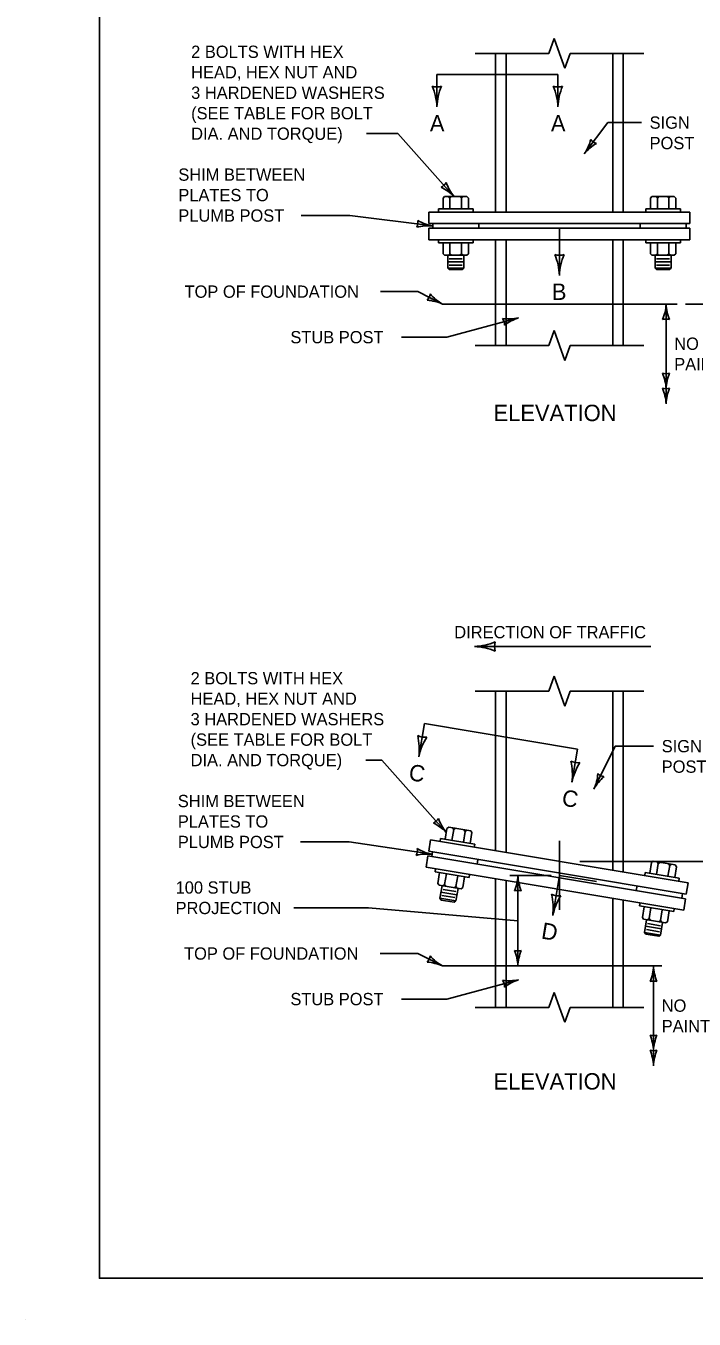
# Model space of a CAD drawing. Extents: x 49991.4 to 50021, y 49987.6 to 50011.4.
# Drawn here: x 49999.02 to 50002.29, y 49987.6 to 49993.92 of the extents above; entities that cross this region are included whole.
import ezdxf

# ---------------------------------------------------------------- set-up
doc = ezdxf.new("R2010")
doc.units = 0
for name, color, linetype in [('Level 1', 7, 'Continuous'), ('Level 2', 7, 'Continuous'), ('Level 3', 7, 'Continuous'), ('Level 5', 7, 'Continuous'), ('Level 6', 7, 'Continuous')]:
    doc.layers.add(name, color=color, linetype=linetype)

msp = doc.modelspace()

# ---------------------------------------------------------------- linework, layer by layer
at = {"layer": 'Level 1'}
for p, q in [((50001.3176, 49993.7824), (50001.3176, 49993.0073)), ((50001.3693, 49993.7824), (50001.3693, 49993.0073)), ((50001.8899, 49993.7824), (50001.8899, 49993.0073)), ((50001.9416, 49993.7824), (50001.9416, 49993.0073)), ((50001.069, 49993.0832), (50001.0615, 49993.0757)), ((50001.0615, 49993.0223), (50001.0615, 49993.0757)), ((50001.069, 49993.0832), (50001.1777, 49993.0832)), ((50001.0877, 49993.0832), (50001.0952, 49993.0757)), ((50001.1028, 49993.0832), (50001.0952, 49993.0757)), ((50001.0952, 49993.0223), (50001.0952, 49993.0757)), ((50001.144, 49993.0832), (50001.1515, 49993.0757)), ((50001.159, 49993.0832), (50001.1515, 49993.0757)), ((50001.1515, 49993.0223), (50001.1515, 49993.0757)), ((50001.1777, 49993.0832), (50001.1852, 49993.0757)), ((50001.1852, 49993.0757), (50001.1852, 49993.0223)), ((50002.0815, 49993.0832), (50002.074, 49993.0757)), ((50002.074, 49993.0757), (50002.074, 49993.0223)), ((50002.1902, 49993.0832), (50002.0815, 49993.0832)), ((50002.1002, 49993.0832), (50002.1077, 49993.0757)), ((50002.1152, 49993.0832), (50002.1077, 49993.0757)), ((50002.1077, 49993.0223), (50002.1077, 49993.0757)), ((50002.1564, 49993.0832), (50002.164, 49993.0757)), ((50002.1715, 49993.0832), (50002.164, 49993.0757)), ((50002.164, 49993.0223), (50002.164, 49993.0757)), ((50002.1902, 49993.0832), (50002.1977, 49993.0757)), ((50002.1977, 49993.0223), (50002.1977, 49993.0757)), ((50000.9922, 49993.0073), (50002.267, 49993.0073)), ((50000.9922, 49993.0073), (50000.9922, 49992.9512)), ((50001.039, 49993.0223), (50001.2077, 49993.0223)), ((50001.039, 49993.0223), (50001.039, 49993.0073)), ((50001.2077, 49993.0223), (50001.2077, 49993.0073)), ((50002.2202, 49993.0223), (50002.0515, 49993.0223)), ((50002.0515, 49993.0223), (50002.0515, 49993.0073)), ((50002.2202, 49993.0223), (50002.2202, 49993.0073)), ((50002.267, 49993.0073), (50002.267, 49992.9512)), ((50000.9922, 49992.9512), (50002.267, 49992.9512)), ((50000.9922, 49992.928), (50002.267, 49992.928)), ((50000.9922, 49992.928), (50000.9922, 49992.8717)), ((50001.0109, 49992.928), (50001.0109, 49992.9512)), ((50001.2359, 49992.928), (50001.2359, 49992.9512)), ((50002.0233, 49992.928), (50002.0233, 49992.9512)), ((50002.2483, 49992.928), (50002.2483, 49992.9512)), ((50002.267, 49992.928), (50002.267, 49992.8717)), ((50002.267, 49992.8717), (50000.9922, 49992.8717)), ((50001.039, 49992.8568), (50001.039, 49992.8717)), ((50001.039, 49992.8568), (50001.2077, 49992.8568)), ((50001.0615, 49992.8568), (50001.0615, 49992.8033)), ((50001.0952, 49992.8568), (50001.0952, 49992.8033)), ((50001.1515, 49992.8568), (50001.1515, 49992.8033)), ((50001.1852, 49992.8033), (50001.1852, 49992.8568)), ((50001.2077, 49992.8568), (50001.2077, 49992.8717)), ((50001.3176, 49992.8717), (50001.3176, 49992.3555)), ((50001.3693, 49992.8717), (50001.3693, 49992.3555)), ((50001.8899, 49992.8717), (50001.8899, 49992.3555)), ((50001.9416, 49992.8717), (50001.9416, 49992.3555)), ((50002.0515, 49992.8568), (50002.0515, 49992.8717)), ((50002.2202, 49992.8568), (50002.0515, 49992.8568)), ((50002.074, 49992.8033), (50002.074, 49992.8568)), ((50002.1077, 49992.8568), (50002.1077, 49992.8033)), ((50002.164, 49992.8568), (50002.164, 49992.8033)), ((50002.1977, 49992.8568), (50002.1977, 49992.8033)), ((50002.2202, 49992.8568), (50002.2202, 49992.8717)), ((50001.069, 49992.7959), (50001.0615, 49992.8033)), ((50001.069, 49992.7959), (50001.1777, 49992.7959)), ((50001.084, 49992.7335), (50001.084, 49992.7959)), ((50001.0877, 49992.7959), (50001.0952, 49992.8033)), ((50001.1028, 49992.7959), (50001.0952, 49992.8033)), ((50001.144, 49992.7959), (50001.1515, 49992.8033)), ((50001.159, 49992.7959), (50001.1515, 49992.8033)), ((50001.1628, 49992.7959), (50001.1628, 49992.7335)), ((50001.1777, 49992.7959), (50001.1852, 49992.8033)), ((50002.0815, 49992.7959), (50002.074, 49992.8033)), ((50002.1902, 49992.7959), (50002.0815, 49992.7959)), ((50002.0964, 49992.7959), (50002.0964, 49992.7335)), ((50002.1002, 49992.7959), (50002.1077, 49992.8033)), ((50002.1152, 49992.7959), (50002.1077, 49992.8033)), ((50002.1564, 49992.7959), (50002.164, 49992.8033)), ((50002.1715, 49992.7959), (50002.164, 49992.8033)), ((50002.1752, 49992.7335), (50002.1752, 49992.7959)), ((50002.1902, 49992.7959), (50002.1977, 49992.8033)), ((50001.084, 49992.7635), (50001.1628, 49992.7635)), ((50001.0915, 49992.7259), (50001.084, 49992.7335)), ((50001.084, 49992.7335), (50001.1628, 49992.7335)), ((50001.0915, 49992.7784), (50001.1552, 49992.7784)), ((50001.0915, 49992.7484), (50001.1552, 49992.7484)), ((50001.0915, 49992.7259), (50001.1552, 49992.7259)), ((50001.1552, 49992.7259), (50001.1628, 49992.7335)), ((50002.1752, 49992.7635), (50002.0964, 49992.7635)), ((50002.104, 49992.7259), (50002.0964, 49992.7335)), ((50002.1752, 49992.7335), (50002.0964, 49992.7335)), ((50002.1677, 49992.7784), (50002.104, 49992.7784)), ((50002.1677, 49992.7484), (50002.104, 49992.7484)), ((50002.1677, 49992.7259), (50002.104, 49992.7259)), ((50002.1677, 49992.7259), (50002.1752, 49992.7335)), ((50002.2046, 49992.5575), (50001.0586, 49992.5575)), ((50001.3176, 49990.6669), (50001.3176, 49989.8871)), ((50001.3693, 49990.6669), (50001.3693, 49989.8784)), ((50001.8899, 49990.6669), (50001.8899, 49989.7918)), ((50001.9416, 49990.6669), (50001.9416, 49989.7832)), ((50001.0494, 49989.9471), (50001.047, 49989.9322)), ((50001.0494, 49989.9471), (50001.216, 49989.9192)), ((50001.0717, 49989.9432), (50001.0804, 49989.996)), ((50001.089, 49990.0022), (50001.0804, 49989.996)), ((50001.089, 49990.0022), (50001.1963, 49989.9843)), ((50001.105, 49989.9377), (50001.1137, 49989.9904)), ((50001.1076, 49989.999), (50001.1137, 49989.9904)), ((50001.1224, 49989.9965), (50001.1137, 49989.9904)), ((50001.1605, 49989.9286), (50001.1692, 49989.9812)), ((50001.163, 49989.9898), (50001.1692, 49989.9812)), ((50001.1778, 49989.9874), (50001.1692, 49989.9812)), ((50001.2025, 49989.9756), (50001.1938, 49989.923)), ((50001.1963, 49989.9843), (50001.2025, 49989.9756)), ((50001.0008, 49989.9399), (50000.9916, 49989.8844)), ((50000.9916, 49989.8844), (50002.2492, 49989.6749)), ((50001.0008, 49989.9399), (50002.2584, 49989.7304)), ((50001.0062, 49989.8585), (50001.01, 49989.8813)), ((50001.216, 49989.9192), (50001.2134, 49989.9045)), ((50000.9877, 49989.8616), (50000.9785, 49989.8062)), ((50000.9877, 49989.8616), (50002.2453, 49989.6521)), ((50001.2282, 49989.8216), (50001.232, 49989.8444)), ((50002.0792, 49989.8296), (50002.0704, 49989.7769)), ((50002.0879, 49989.8357), (50002.0792, 49989.8296)), ((50002.195, 49989.8178), (50002.0879, 49989.8357)), ((50002.1037, 49989.7714), (50002.1125, 49989.824)), ((50002.1064, 49989.8326), (50002.1125, 49989.824)), ((50002.1211, 49989.8302), (50002.1125, 49989.824)), ((50002.1618, 49989.8235), (50002.1679, 49989.8148)), ((50002.1766, 49989.821), (50002.1679, 49989.8148)), ((50002.195, 49989.8178), (50002.2012, 49989.8092)), ((50000.9785, 49989.8062), (50002.2362, 49989.5967)), ((50001.0223, 49989.7836), (50001.0247, 49989.7985)), ((50001.0223, 49989.7836), (50001.1887, 49989.7559)), ((50001.0445, 49989.78), (50001.0357, 49989.7274)), ((50001.0777, 49989.7745), (50001.069, 49989.7217)), ((50001.1332, 49989.7652), (50001.1245, 49989.7126)), ((50001.1578, 49989.707), (50001.1665, 49989.7596)), ((50001.1887, 49989.7559), (50001.1912, 49989.7707)), ((50002.0483, 49989.7806), (50002.0458, 49989.7659)), ((50002.2146, 49989.7529), (50002.0483, 49989.7806)), ((50002.1592, 49989.762), (50002.1679, 49989.8148)), ((50002.1925, 49989.7565), (50002.2012, 49989.8092)), ((50002.2146, 49989.7529), (50002.2122, 49989.738)), ((50001.0418, 49989.7187), (50001.0357, 49989.7274)), ((50001.0418, 49989.7187), (50001.1491, 49989.7008)), ((50001.0464, 49989.6546), (50001.0566, 49989.7162)), ((50001.0603, 49989.7156), (50001.069, 49989.7217)), ((50001.0612, 49989.6977), (50001.124, 49989.6873)), ((50001.0751, 49989.7131), (50001.069, 49989.7217)), ((50001.1159, 49989.7064), (50001.1245, 49989.7126)), ((50001.1344, 49989.7032), (50001.124, 49989.6417)), ((50001.1306, 49989.704), (50001.1245, 49989.7126)), ((50001.1491, 49989.7008), (50001.1578, 49989.707)), ((50001.3176, 49989.7497), (50001.3176, 49989.122)), ((50001.3693, 49989.741), (50001.3693, 49989.122)), ((50002.005, 49989.6922), (50002.0087, 49989.715)), ((50002.2584, 49989.7304), (50002.2492, 49989.6749)), ((50001.0525, 49989.646), (50001.0464, 49989.6546)), ((50001.0464, 49989.6546), (50001.124, 49989.6417)), ((50001.0513, 49989.6843), (50001.129, 49989.6713)), ((50001.0525, 49989.646), (50001.1154, 49989.6356)), ((50001.0562, 49989.6682), (50001.1191, 49989.6578)), ((50001.1154, 49989.6356), (50001.124, 49989.6417)), ((50001.8899, 49989.6543), (50001.8899, 49989.122)), ((50001.9416, 49989.6456), (50001.9416, 49989.122)), ((50002.0209, 49989.6173), (50002.0234, 49989.6321)), ((50002.2268, 49989.6552), (50002.2307, 49989.678)), ((50002.2453, 49989.6521), (50002.2362, 49989.5967)), ((50002.1875, 49989.5895), (50002.0209, 49989.6173)), ((50002.0344, 49989.5609), (50002.0432, 49989.6136)), ((50002.0765, 49989.608), (50002.0677, 49989.5554)), ((50002.132, 49989.5988), (50002.1232, 49989.5462)), ((50002.1653, 49989.5932), (50002.1565, 49989.5405)), ((50002.1875, 49989.5895), (50002.1899, 49989.6044)), ((50002.0406, 49989.5523), (50002.0344, 49989.5609)), ((50002.1479, 49989.5344), (50002.0406, 49989.5523)), ((50002.0554, 49989.5499), (50002.0452, 49989.4882)), ((50002.1277, 49989.5049), (50002.05, 49989.5178)), ((50002.1179, 49989.4913), (50002.055, 49989.5018)), ((50002.0591, 49989.5492), (50002.0677, 49989.5554)), ((50002.1228, 49989.5208), (50002.0599, 49989.5314)), ((50002.0738, 49989.5468), (50002.0677, 49989.5554)), ((50002.1145, 49989.54), (50002.1232, 49989.5462)), ((50002.1228, 49989.4752), (50002.133, 49989.5369)), ((50002.1294, 49989.5375), (50002.1232, 49989.5462)), ((50002.1479, 49989.5344), (50002.1565, 49989.5405)), ((50002.0513, 49989.4796), (50002.0452, 49989.4882)), ((50002.1228, 49989.4752), (50002.0452, 49989.4882)), ((50002.1142, 49989.4691), (50002.0513, 49989.4796)), ((50002.1142, 49989.4691), (50002.1228, 49989.4752)), ((50002.129, 49989.324), (50001.0586, 49989.324)), ((49999.0245, 49987.5988), (49999.0245, 49987.5988))]:
    msp.add_line(p, q, dxfattribs=at)
msp.add_lwpolyline([(49999.3835, 49998.9992), (50016.7501, 49998.9992), (50016.7501, 49987.7988), (49999.3835, 49987.7988)], close=True, dxfattribs=at)
at = {"layer": 'Level 3'}
for p, q in [((50001.7508, 49993.2915), (50001.8658, 49993.4442)), ((50001.8658, 49993.4442), (50002.0299, 49993.4442)), ((50000.8398, 49993.3901), (50000.6876, 49993.3901)), ((50001.1148, 49993.0832), (50000.8398, 49993.3901)), ((50000.3679, 49992.9901), (50000.6057, 49992.9901)), ((50001.0109, 49992.9396), (50000.6057, 49992.9901)), ((50000.9384, 49992.6184), (50000.756, 49992.6184)), ((50001.0586, 49992.5575), (50000.9384, 49992.6184)), ((50002.1501, 49992.5575), (50002.1501, 49992.0704)), ((50002.2446, 49992.5575), (50002.5649, 49992.5575)), ((50001.0796, 49992.3959), (50001.4302, 49992.4906)), ((50001.0796, 49992.3959), (50000.8577, 49992.3959)), ((50002.0762, 49990.8848), (50001.2147, 49990.8848)), ((50001.9023, 49990.3979), (50001.7983, 49990.1885)), ((50002.089, 49990.3979), (50001.9023, 49990.3979)), ((50000.7619, 49990.3299), (50000.685, 49990.3299)), ((50001.0772, 49989.9768), (50000.7619, 49990.3299)), ((50000.3654, 49989.9299), (50000.6029, 49989.9299)), ((50001.0081, 49989.8699), (50000.6029, 49989.9299)), ((50001.7296, 49989.8352), (50002.4683, 49989.8352)), ((50001.5896, 49989.7664), (50001.3867, 49989.7664)), ((50001.4267, 49989.7664), (50001.4267, 49989.324)), ((50000.6981, 49989.6074), (50000.3335, 49989.6074)), ((50001.4267, 49989.5452), (50000.6981, 49989.6074)), ((50000.9384, 49989.3849), (50000.7536, 49989.3849)), ((50001.0586, 49989.324), (50000.9384, 49989.3849)), ((50002.089, 49989.324), (50002.089, 49988.8369)), ((50001.0796, 49989.1624), (50001.4302, 49989.2571)), ((50001.0796, 49989.1624), (50000.8577, 49989.1624))]:
    msp.add_line(p, q, dxfattribs=at)
for centre, radius, start, end in [((50001.558, 49993.4223), 0.233, 325.84352, 345.09337), ((50001.8279, 49993.3939), 0.0548, 215.15503, 250.87739), ((50001.9227, 49993.1506), 0.2223, 120.47222, 140.65572), ((50001.0293, 49993.1787), 0.0548, 294.00341, 329.72577), ((50000.9492, 49992.9193), 0.233, 44.6919, 63.94175), ((50001.2864, 49993.2246), 0.2223, 199.3206, 219.50411), ((50000.8838, 49992.9568), 0.0548, 334.44826, 10.17063), ((50000.9911, 49992.7074), 0.233, 85.13676, 104.38661), ((50001.0497, 49993.1585), 0.2223, 239.76546, 259.94896), ((50000.9442, 49992.6154), 0.0548, 315.26951, 350.99187), ((50001.1672, 49992.7515), 0.2223, 220.5867, 240.77021), ((50000.9637, 49992.3447), 0.233, 65.958, 85.20785), ((50001.928, 49992.5667), 0.2223, 337.45601, 357.63952), ((50002.3828, 49992.569), 0.233, 182.82731, 202.07716), ((50001.3811, 49992.7074), 0.2223, 262.57138, 282.75488), ((50001.3064, 49992.4572), 0.0548, 357.25418, 32.97654), ((50001.502, 49992.2689), 0.233, 107.94268, 127.19253), ((50002.1501, 49992.4293), 0.0548, 72.13882, 107.86118), ((50002.1501, 49992.2721), 0.0548, 252.13882, 287.86118), ((50001.9174, 49992.1323), 0.233, 2.82731, 22.07716), ((50002.3722, 49992.1347), 0.2223, 157.45601, 177.63952), ((50002.1501, 49992.1986), 0.0548, 252.13882, 287.86118), ((50001.9174, 49992.0589), 0.233, 2.82731, 22.07716), ((50002.3722, 49992.0612), 0.2223, 157.45601, 177.63952), ((50001.1994, 49991.1951), 0.3107, 272.82731, 292.07716), ((50001.3857, 49990.8848), 0.073, 162.13882, 197.86118), ((50001.2025, 49990.5886), 0.2964, 67.45601, 87.63952), ((50001.5848, 49990.2817), 0.233, 336.41569, 355.66554), ((50001.8553, 49990.3033), 0.0548, 225.7272, 261.44956), ((50001.9932, 49990.0815), 0.2223, 131.04439, 151.2279), ((50000.9918, 49990.0724), 0.0548, 293.90202, 329.62438), ((50000.9113, 49989.8132), 0.233, 44.59051, 63.84036), ((50001.249, 49990.1179), 0.2223, 199.21921, 219.40272), ((50000.8812, 49989.8885), 0.0548, 333.78807, 9.51043), ((50001.0494, 49990.0883), 0.2223, 239.10526, 259.28877), ((50000.9857, 49989.638), 0.233, 84.47656, 103.72641), ((50001.2046, 49989.7756), 0.2223, 337.45601, 357.63952), ((50001.6594, 49989.7779), 0.233, 182.82731, 202.07716), ((50001.4267, 49989.6382), 0.0548, 72.13882, 107.86118), ((50000.9442, 49989.3819), 0.0548, 315.26951, 350.99187), ((50001.1672, 49989.518), 0.2223, 220.5867, 240.77021), ((50001.4267, 49989.4522), 0.0548, 252.13882, 287.86118), ((50001.194, 49989.3125), 0.233, 2.82731, 22.07716), ((50001.6488, 49989.3148), 0.2223, 157.45601, 177.63952), ((50000.9637, 49989.1112), 0.233, 65.958, 85.20785), ((50001.8669, 49989.3332), 0.2223, 337.45601, 357.63952), ((50002.3217, 49989.3355), 0.233, 182.82731, 202.07716), ((50001.3811, 49989.4739), 0.2223, 262.57138, 282.75488), ((50001.3064, 49989.2237), 0.0548, 357.25418, 32.97654), ((50001.502, 49989.0354), 0.233, 107.94268, 127.19253), ((50002.089, 49989.1958), 0.0548, 72.13882, 107.86118), ((50002.089, 49989.0386), 0.0548, 252.13882, 287.86118), ((50001.8563, 49988.8988), 0.233, 2.82731, 22.07716), ((50002.3112, 49988.9012), 0.2223, 157.45601, 177.63952), ((50002.089, 49988.9651), 0.0548, 252.13882, 287.86118), ((50001.8563, 49988.8254), 0.233, 2.82731, 22.07716), ((50002.3112, 49988.8277), 0.2223, 157.45601, 177.63952)]:
    msp.add_arc(centre, radius, start, end, dxfattribs=at)
at = {"layer": 'Level 5'}
msp.add_line((50001.6296, 49989.5977), (50001.6296, 49989.9352), dxfattribs=at)
at = {"layer": 'Level 6'}
for p, q in [((50001.6037, 49993.8555), (50001.5778, 49993.7824)), ((50001.6037, 49993.8555), (50001.6296, 49993.7824)), ((50001.2176, 49993.7824), (50001.5778, 49993.7824)), ((50001.6296, 49993.7824), (50001.6555, 49993.7093)), ((50001.6814, 49993.7824), (50001.6555, 49993.7093)), ((50001.6814, 49993.7824), (50002.0416, 49993.7824)), ((50001.0313, 49993.6789), (50001.6222, 49993.6789)), ((50001.0313, 49993.6789), (50001.0313, 49993.5207)), ((50001.6222, 49993.6789), (50001.6222, 49993.5207)), ((50001.6037, 49992.4286), (50001.5778, 49992.3555)), ((50001.6037, 49992.4286), (50001.6296, 49992.3555)), ((50001.2176, 49992.3555), (50001.5778, 49992.3555)), ((50001.6296, 49992.3555), (50001.6555, 49992.2824)), ((50001.6814, 49992.3555), (50001.6555, 49992.2824)), ((50001.6814, 49992.3555), (50002.0416, 49992.3555)), ((50001.6037, 49990.74), (50001.5778, 49990.6669)), ((50001.6037, 49990.74), (50001.6296, 49990.6669)), ((50001.2176, 49990.6669), (50001.5778, 49990.6669)), ((50001.6296, 49990.6669), (50001.6555, 49990.5938)), ((50001.6814, 49990.6669), (50001.6555, 49990.5938)), ((50001.6814, 49990.6669), (50002.0416, 49990.6669)), ((50000.9701, 49990.5084), (50000.943, 49990.3458)), ((50000.9701, 49990.5084), (50001.7178, 49990.3839)), ((50001.7178, 49990.3839), (50001.6907, 49990.2214)), ((50001.5969, 49989.5704), (50001.6296, 49989.7664)), ((50001.6296, 49989.7664), (50001.8107, 49989.7363)), ((50001.6037, 49989.1951), (50001.5778, 49989.122)), ((50001.6037, 49989.1951), (50001.6296, 49989.122)), ((50001.2176, 49989.122), (50001.5778, 49989.122)), ((50001.6296, 49989.122), (50001.6555, 49989.0489)), ((50001.6814, 49989.122), (50001.6555, 49989.0489)), ((50001.6814, 49989.122), (50002.0416, 49989.122))]:
    msp.add_line(p, q, dxfattribs=at)
msp.add_lwpolyline([(50002.0233, 49992.928), (50001.6296, 49992.928), (50001.6296, 49992.6977)], dxfattribs=at)
for centre, radius, start, end in [((50001.0313, 49993.6917), 0.073, 252.13882, 287.86118), ((50000.721, 49993.5054), 0.3107, 2.82731, 22.07716), ((50001.3275, 49993.5085), 0.2964, 157.45601, 177.63952), ((50001.6222, 49993.6917), 0.073, 252.13882, 287.86118), ((50001.3119, 49993.5054), 0.3107, 2.82731, 22.07716), ((50001.9184, 49993.5085), 0.2964, 157.45601, 177.63952), ((50001.6296, 49992.8687), 0.073, 252.13882, 287.86118), ((50001.3193, 49992.6824), 0.3107, 2.82731, 22.07716), ((50001.9258, 49992.6855), 0.2964, 157.45601, 177.63952), ((50000.9711, 49990.5144), 0.073, 242.6765, 278.39886), ((50000.6344, 49990.3817), 0.3107, 353.36499, 12.61484), ((50001.2331, 49990.2851), 0.2964, 147.99369, 168.1772), ((50001.7188, 49990.39), 0.073, 242.67078, 278.39314), ((50001.3821, 49990.2573), 0.3107, 353.35927, 12.60912), ((50001.9808, 49990.1606), 0.2964, 147.98797, 168.17148), ((50001.625, 49989.739), 0.073, 242.66702, 278.38938), ((50001.2883, 49989.6063), 0.3107, 353.35551, 12.60536), ((50001.887, 49989.5096), 0.2964, 147.98421, 168.16772)]:
    msp.add_arc(centre, radius, start, end, dxfattribs=at)

# ---------------------------------------------------------------- texts
at = {"layer": 'Level 2'}
for s, height, p in [('2 BOLTS WITH HEX', 0.06, (49999.8314, 49993.7601)), ('HEAD, HEX NUT AND', 0.06, (49999.8314, 49993.6601)), ('3 HARDENED WASHERS', 0.06, (49999.8314, 49993.5601)), ('(SEE TABLE FOR BOLT', 0.06, (49999.8314, 49993.4601)), ('A', 0.08, (50000.997, 49993.4007)), ('A', 0.08, (50001.5879, 49993.4007)), ('DIA. AND TORQUE)', 0.06, (49999.8314, 49993.3601)), ('SIGN', 0.06, (50002.0699, 49993.4142)), ('POST', 0.06, (50002.0699, 49993.3142)), ('SHIM BETWEEN', 0.06, (49999.7689, 49993.1601)), ('PLATES TO', 0.06, (49999.7689, 49993.0601)), ('PLUMB POST', 0.06, (49999.7689, 49992.9601)), ('TOP OF FOUNDATION', 0.06, (49999.7993, 49992.5884)), ('B', 0.08, (50001.5926, 49992.5777)), ('STUB POST', 0.06, (50000.316, 49992.3659)), ('NO', 0.06, (50002.1901, 49992.334)), ('PAINT', 0.06, (50002.1901, 49992.234)), ('ELEVATION', 0.08, (50001.3079, 49991.9858)), ('DIRECTION OF TRAFFIC', 0.06, (50001.1162, 49990.9248)), ('2 BOLTS WITH HEX', 0.06, (49999.8288, 49990.6999)), ('HEAD, HEX NUT AND', 0.06, (49999.8288, 49990.5999)), ('3 HARDENED WASHERS', 0.06, (49999.8288, 49990.4999)), ('(SEE TABLE FOR BOLT', 0.06, (49999.8288, 49990.3999)), ('SIGN', 0.06, (50002.129, 49990.3679)), ('DIA. AND TORQUE)', 0.06, (49999.8288, 49990.2999)), ('POST', 0.06, (50002.129, 49990.2679)), ('SHIM BETWEEN', 0.06, (49999.7664, 49990.0999)), ('PLATES TO', 0.06, (49999.7664, 49989.9999)), ('PLUMB POST', 0.06, (49999.7664, 49989.8999)), ('100 STUB', 0.06, (49999.7555, 49989.6774)), ('PROJECTION', 0.06, (49999.7555, 49989.5774)), ('TOP OF FOUNDATION', 0.06, (49999.7969, 49989.3549)), ('STUB POST', 0.06, (50000.316, 49989.1324)), ('NO', 0.06, (50002.129, 49989.1004)), ('PAINT', 0.06, (50002.129, 49989.0004)), ('ELEVATION', 0.08, (50001.3079, 49988.7204))]:
    msp.add_text(s, height=height, dxfattribs=at).set_placement(p)
for s, p in [('C', (50000.8897, 49990.233)), ('C', (50001.6374, 49990.1086)), ('D', (50001.5373, 49989.4587))]:
    msp.add_text(s, height=0.08, rotation=350.55, dxfattribs=at).set_placement(p)

doc.saveas('drawing.dxf')
